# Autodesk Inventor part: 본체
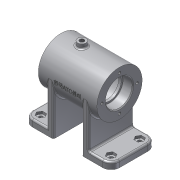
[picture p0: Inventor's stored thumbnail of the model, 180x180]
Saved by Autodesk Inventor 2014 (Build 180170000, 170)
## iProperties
Created: 2017-02
Part Number: 본체
Material: 알루미늄 6061
Document SubType Name: Modeling
Designer: SCD-A14
Density: 2.71 g/cm^3
Appearance: 알루미늄 - 평지
Mass: 355.995 g
Surface Area: 423.11 cm^2
Volume: 131.364 cm^3
Author: SCD-A14
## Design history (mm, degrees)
sketch "스케치1"
  geometry: L1 (-35, 27)-(35, 27); L2 (35, 27)-(35, 0); L3 (35, 0)-(-35, 0); L4 (-35, 0)-(-35, 27); L5 (-35, 0)-(-23, 0); L6 (-23, 0)-(-23, 16); L7 (-23, 16)-(-35, 16); L8 (-35, 16)-(-35, 0); L9 (-23, 0)-(-20, 0); L10 (-20, 0)-(-20, 14); L11 (-20, 14)-(-23, 14); L12 (-23, 14)-(-23, 0); L13 (-20, 0)-(20, 0); L14 (20, 0)-(20, 22); L15 (20, 22)-(-20, 22); L16 (-20, 22)-(-20, 0); L17 (20, 0)-(23, 0); L18 (23, 0)-(23, 14); L19 (23, 14)-(20, 14); L20 (20, 14)-(20, 0); L21 (23, 0)-(35, 0); L22 (35, 0)-(35, 16); L23 (35, 16)-(23, 16); L24 (23, 16)-(23, 0); 2 further points
  constraints: 48 end point, 12 parallel, 6 horizontal, 6 perpendicular, 1 coincident, 1 midpoint
  dimensions: "d2" = 27 distance of L1.end L2.end; "d3" = 70 distance of L1.start L1.end; "d4" = 12 distance of L7.end L6.end; "d6" = 3 distance of L11.end L10.end; "d8" = 40 distance of L15.end L14.end; "d10" = 3 distance of L19.end L18.end; "d12" = 12 distance of L23.end L22.end; "d96" = 32 diameter of L7 L3; "d97" = 28 diameter of L11 L9; "d98" = 44 diameter of L15 L13; "d99" = 28 diameter of L19 L3; "d100" = 32 diameter of L23 L3
revolve "회전1" sketch "스케치1" stored, may be unused: angle "d14" = 90 deg
chamfer "모따기1" distance "d15" = 1; stored, may be unused: second distance "d16" = 2, angle "d17" = 45 deg
fillet "모깎기1" dims "d18" = 3, "d19" = 0.3
node "작업 평면1"
sketch "스케치2"
  geometry: L1 (42, 27)-(-42, 27); L2 (-52, 17)-(-52, -17); L3 (-42, -27)-(42, -27); L4 (52, -17)-(52, 17); L5 (35, 27)-(35, -27) reference; L6 (-35, 27)-(-35, -27) reference; L7 (35, 27)-(35, -27) reference; L8 (35, 27)-(-35, 27) reference; L9 (35, -27)-(-35, -27) reference; L10 (0, 27)-(0, -27); L11 (0, -27)-(17, -27); L12 (17, -27)-(17, 27); L13 (0, 27)-(17, 27); L14 (0, -27)-(-17, -27); L15 (-17, -27)-(-17, 27); L16 (-17, 27)-(0, 27); L17 (0, 27)-(0, -27); L18 (17, 27)-(0, 27); L19 (17, -27)-(0, -27); A1 r 10 centre (42, 17) between (52, 17) and (42, 27); A2 r 10 centre (42, -17) between (42, -27) and (52, -17); A3 r 10 centre (-42, -17) between (-52, -17) and (-42, -27); A4 r 10 centre (-42, 17) between (-42, 27) and (-52, 17); 4 further points
  constraints: 28 end point, 9 point on line, 8 point on circle, 8 tangent, 4 centre point, 4 parallel, 3 collinear, 3 equal radius, 3 perpendicular, 2 horizontal, 2 midpoint
  dimensions: "d21" = 104 distance of point (52, -27) point (-52, -27); "d22" = 54 distance of point (-52, -27) point (-52, 27); "d23" = 10 radius of A1; "d24" = 27 distance from line of point (0, 0) L1; "d25" = 52 distance from line of point (0, 0) L4; "d26" = 17 distance of L10.end L11.end; "d27" = 17 distance of L15.end L16.end
  node "투영된 루프1"
extrude "돌출1" join sketch "스케치2" distance "d28" = 8; taper "d29" = 0 deg
sketch "스케치3"
  geometry: L1 (17, 27)-(17, -27) reference; L2 (17, -27)-(42, -27) reference; L3 (17, 27)-(25, 27); L4 (25, 27)-(25, -27); L5 (25, -27)-(17, -27); L6 (17, -27)-(17, 27); 1 further point
  constraints: 8 end point, 2 parallel, 1 horizontal, 1 perpendicular, 1 point on line
  dimensions: "d30" = 8 distance of L4.end L5.end
extrude "돌출2" join sketch "스케치3" stored distance "d31" = 10; taper "d32" = 0 deg
fillet "모깎기2" dims "d33" = 2
sketch "스케치4"
  geometry: L1 (44.598, -12.5)-(47.196, -17); L2 (47.196, -17)-(44.598, -21.5); L3 (44.598, -21.5)-(39.402, -21.5); L4 (39.402, -21.5)-(36.804, -17); L5 (36.804, -17)-(39.402, -12.5); L6 (39.402, -12.5)-(44.598, -12.5); 3 further points
  constraints: 12 end point, 1 midpoint, 13 other
extrude "돌출3" cut sketch "스케치4" distance "d35" = 3; taper "d36" = 0 deg
hole "구멍1" diameter "d39" = 5; stored, may be unused: countersink angle "d43" = 90 deg, drill point angle "d45" = 118 deg; dims "d37" = 10, "d38" = 10, "d40" = 6, "d41" = 4, "d42" = 2, "d44" = 8
node "작업 평면3"
sketch "스케치5"
  geometry: L1 (35, 27)-(35, -27) reference; C1 r 5 at (10, 0); 1 further point
  constraints: 1 centre point
  dimensions: "d54" = 10 diameter of C1
extrude "돌출4" join sketch "스케치5" stored distance "d55" = 3; taper "d56" = 0 deg
fillet "모깎기3" dims "d57" = 2
hole "구멍2" diameter "d60" = 5.2; stored, may be unused: countersink angle "d64" = 90 deg, drill point angle "d66" = 118 deg; dims "d58" = 10, "d59" = 10, "d61" = 6, "d62" = 4, "d63" = 2, "d65" = 15
sketch "스케치6"
  geometry: 1 further point
hole "구멍3" sketch "스케치6" at (0, 21) diameter "d68" = 3.2; stored, may be unused: countersink angle "d72" = 90 deg, drill point angle "d74" = 118 deg; dims "d69" = 8, "d70" = 4, "d71" = 2, "d73" = 10
node "작업 평면4"
sketch "스케치7"
  geometry: L1 (0, 0)-(-16.339, -25.16); L2 (0, 0)-(0, -10.772)
  constraints: 4 end point, 1 vertical
  dimensions: "d78" = 30 distance of L1.start L1.end; "d101" = 33 deg angle of L2 L1
node "작업 평면5"
sketch "스케치8"
  geometry: C1 r 6 at (0, 0); 1 further point
  constraints: 1 centre point, 1 coincident
  dimensions: "d80" = 12 diameter of C1
extrude "돌출5" join sketch "스케치8" stored distance "d81" = 3; taper "d82" = 0 deg
hole "구멍4" diameter "d85" = 5.2; stored, may be unused: countersink angle "d89" = 90 deg, drill point angle "d91" = 118 deg; dims "d83" = 10, "d84" = 10, "d86" = 8, "d87" = 4, "d88" = 2, "d90" = 10
node "작업 평면6"
sketch "스케치9"
  geometry: L1 (-35, -27)-(-35, 27) reference; L2 (-35, 27)-(35, 27) reference; 2 further points
  constraints: 1 coincident, 1 other
feature "엠보싱1" sketch "스케치9" dims "d2" = 27, "d3" = 70, "d4" = 12, "d6" = 3, "d8" = 40, "d10" = 3, "d12" = 12, "d93" = 0.5, "d94" = 0, "d96" = 32, "d97" = 28, "d98" = 44, "d99" = 28, "d100" = 32
fillet "모깎기4" dims "d95" = 2
extrude "돌출6" cut sketch "스케치2" distance "d102" = 8; taper "d103" = 0 deg
fillet "모깎기5" dims "d104" = 2
node "솔리드1"
mirror "대칭3"
pattern_linear "직사각형 패턴1" dims "d48" = 34, "d51" = 84
pattern_circular "원형 패턴1" dims angle "d76" = 360 deg
mirror "대칭5"
other parameters: "d52" = 32, "d92" = 39.25
